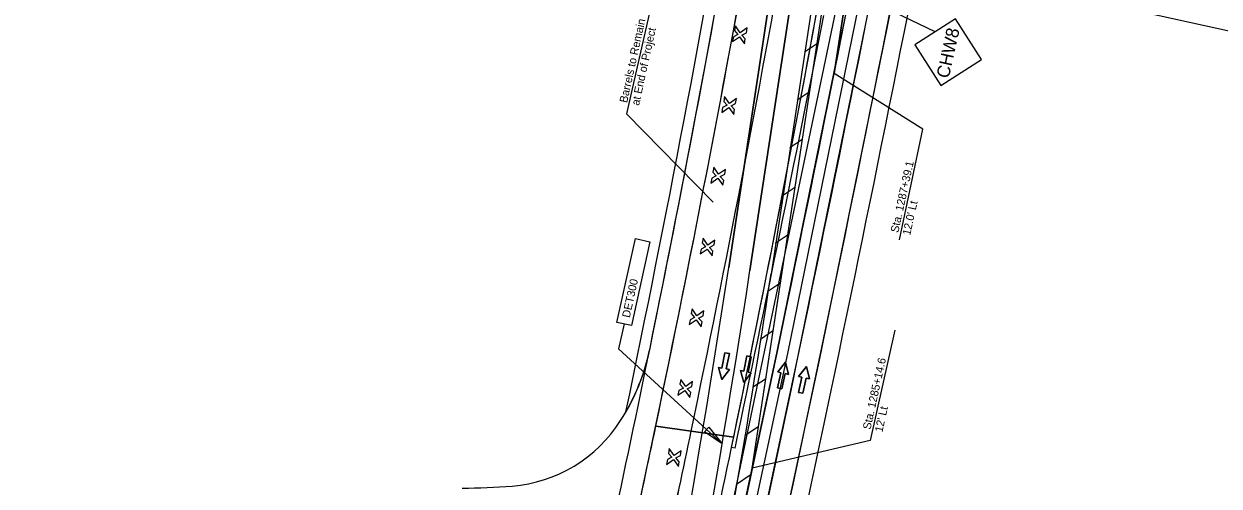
# Model space of a CAD drawing. Extents: x 14104283 to 14120882, y 8635219 to 8671666.
# Drawn here: x 14107490 to 14108160, y 8639477 to 8639736 of the extents above; entities that cross this region are included whole.
import ezdxf

# ---------------------------------------------------------------- set-up
doc = ezdxf.new("R2010")
doc.units = 0
for name, color, linetype in [('Cell', 7, 'Continuous'), ('dsnNonPlotable', 7, 'Continuous'), ('dsnPaintExistingBrokenLaneLineWhite', 7, 'Continuous'), ('dsnPaintExistingEdgeLineRightWhite', 7, 'Continuous'), ('dsnPaintPlaceBrokenLaneWhite', 7, 'Continuous'), ('dsnPaintPlaceChannelizingLaneWhite', 7, 'Continuous'), ('dsnPaintPlaceChannelizingLaneYellow', 7, 'Continuous'), ('dsnPaintPlaceEdgeLineRightWhite', 7, 'Continuous'), ('dsnPaintRemoveEdgeLineWhite', 7, 'Continuous'), ('dsnPaintRemoveEdgeLineYellow', 7, 'Continuous'), ('dsnShadingPaved', 7, 'Continuous'), ('dsnStdLabel', 7, 'Continuous'), ('dsnStgShadingPrevPav', 7, 'Continuous'), ('Text', 7, 'Continuous')]:
    doc.layers.add(name, color=color, linetype=linetype)

msp = doc.modelspace()

# ---------------------------------------------------------------- linework, layer by layer
at = {"layer": 'Cell'}
for p, q in [((14107889.07, 8639734.89), (14107888.6, 8639732.18)), ((14107891.81, 8639730.99), (14107889.07, 8639734.89)), ((14107895.72, 8639733.73), (14107891.81, 8639730.99)), ((14107895.25, 8639731.02), (14107895.72, 8639733.73)), ((14107887.52, 8639726.02), (14107891.43, 8639728.77)), ((14107888, 8639728.73), (14107887.52, 8639726.02)), ((14107890.51, 8639730.07), (14107888, 8639728.73)), ((14107888.6, 8639732.18), (14107890.51, 8639730.07)), ((14107891.43, 8639728.77), (14107894.17, 8639724.86)), ((14107892.73, 8639729.68), (14107895.25, 8639731.02)), ((14107894.65, 8639727.57), (14107892.73, 8639729.68)), ((14107894.17, 8639724.86), (14107894.65, 8639727.57)), ((14107883.03, 8639695.26), (14107882.55, 8639692.56)), ((14107885.77, 8639691.36), (14107883.03, 8639695.26)), ((14107889.68, 8639694.1), (14107885.77, 8639691.36)), ((14107889.2, 8639691.39), (14107889.68, 8639694.1)), ((14107881.48, 8639686.4), (14107885.38, 8639689.14)), ((14107881.95, 8639689.11), (14107881.48, 8639686.4)), ((14107884.47, 8639690.44), (14107881.95, 8639689.11)), ((14107882.55, 8639692.56), (14107884.47, 8639690.44)), ((14107885.38, 8639689.14), (14107888.13, 8639685.24)), ((14107886.68, 8639690.06), (14107889.2, 8639691.39)), ((14107888.6, 8639687.95), (14107886.68, 8639690.06)), ((14107888.13, 8639685.24), (14107888.6, 8639687.95)), ((14107876.96, 8639655.64), (14107876.48, 8639652.93)), ((14107876.48, 8639652.93), (14107878.4, 8639650.82)), ((14107879.7, 8639651.74), (14107876.96, 8639655.64)), ((14107883.61, 8639654.48), (14107879.7, 8639651.74)), ((14107883.13, 8639651.77), (14107883.61, 8639654.48)), ((14107875.41, 8639646.78), (14107879.31, 8639649.52)), ((14107875.88, 8639649.49), (14107875.41, 8639646.78)), ((14107878.4, 8639650.82), (14107875.88, 8639649.49)), ((14107879.31, 8639649.52), (14107882.06, 8639645.62)), ((14107880.62, 8639650.44), (14107883.13, 8639651.77)), ((14107882.53, 8639648.33), (14107880.62, 8639650.44)), ((14107882.06, 8639645.62), (14107882.53, 8639648.33)), ((14107870.97, 8639616.01), (14107870.49, 8639613.3)), ((14107870.49, 8639613.3), (14107872.41, 8639611.19)), ((14107873.71, 8639612.1), (14107870.97, 8639616.01)), ((14107877.62, 8639614.84), (14107873.71, 8639612.1)), ((14107877.14, 8639612.14), (14107877.62, 8639614.84)), ((14107869.42, 8639607.14), (14107873.32, 8639609.88)), ((14107869.89, 8639609.85), (14107869.42, 8639607.14)), ((14107872.41, 8639611.19), (14107869.89, 8639609.85)), ((14107873.32, 8639609.88), (14107876.07, 8639605.98)), ((14107874.63, 8639610.8), (14107877.14, 8639612.14)), ((14107876.54, 8639608.69), (14107874.63, 8639610.8)), ((14107876.07, 8639605.98), (14107876.54, 8639608.69)), ((14107864.82, 8639576.4), (14107864.35, 8639573.69)), ((14107864.35, 8639573.69), (14107866.26, 8639571.58)), ((14107867.56, 8639572.5), (14107864.82, 8639576.4)), ((14107871.47, 8639575.24), (14107867.56, 8639572.5)), ((14107868.48, 8639571.19), (14107871, 8639572.53)), ((14107871, 8639572.53), (14107871.47, 8639575.24)), ((14107863.27, 8639567.54), (14107867.18, 8639570.28)), ((14107863.75, 8639570.24), (14107863.27, 8639567.54)), ((14107866.26, 8639571.58), (14107863.75, 8639570.24)), ((14107867.18, 8639570.28), (14107869.92, 8639566.38)), ((14107870.4, 8639569.08), (14107868.48, 8639571.19)), ((14107869.92, 8639566.38), (14107870.4, 8639569.08)), ((14107858.48, 8639536.84), (14107858.01, 8639534.13)), ((14107858.01, 8639534.13), (14107859.93, 8639532.02)), ((14107861.23, 8639532.94), (14107858.48, 8639536.84)), ((14107865.13, 8639535.68), (14107861.23, 8639532.94)), ((14107862.14, 8639531.63), (14107864.66, 8639532.97)), ((14107864.66, 8639532.97), (14107865.13, 8639535.68)), ((14107856.93, 8639527.97), (14107860.84, 8639530.72)), ((14107857.41, 8639530.68), (14107856.93, 8639527.97)), ((14107859.93, 8639532.02), (14107857.41, 8639530.68)), ((14107860.84, 8639530.72), (14107863.58, 8639526.81)), ((14107864.06, 8639529.52), (14107862.14, 8639531.63)), ((14107863.58, 8639526.81), (14107864.06, 8639529.52)), ((14107853.51, 8639493.28), (14107850.99, 8639491.94)), ((14107852.07, 8639498.1), (14107851.59, 8639495.39)), ((14107851.59, 8639495.39), (14107853.51, 8639493.28)), ((14107854.81, 8639494.19), (14107852.07, 8639498.1)), ((14107858.71, 8639496.93), (14107854.81, 8639494.19)), ((14107855.72, 8639492.89), (14107858.24, 8639494.23)), ((14107857.64, 8639490.78), (14107855.72, 8639492.89)), ((14107858.24, 8639494.23), (14107858.71, 8639496.93)), ((14107850.52, 8639489.23), (14107854.42, 8639491.97)), ((14107850.99, 8639491.94), (14107850.52, 8639489.23)), ((14107854.42, 8639491.97), (14107857.17, 8639488.07)), ((14107857.17, 8639488.07), (14107857.64, 8639490.78))]:
    msp.add_line(p, q, dxfattribs=at)
for points in [[(14107883.26, 8639551.82), (14107885.71, 8639551.33), (14107884, 8639542.75), (14107885.84, 8639542.38), (14107881.55, 8639536.86), (14107879.71, 8639543.61), (14107881.55, 8639543.24)], [(14107895.45, 8639550.04), (14107897.9, 8639549.55), (14107896.18, 8639540.97), (14107898.02, 8639540.6), (14107893.73, 8639535.09), (14107891.89, 8639541.83), (14107893.73, 8639541.46)], [(14107915.2, 8639531.54), (14107912.75, 8639532.07), (14107914.62, 8639540.62), (14107912.79, 8639541.02), (14107917.17, 8639546.46), (14107918.89, 8639539.69), (14107917.06, 8639540.09)], [(14107926.93, 8639529.08), (14107924.49, 8639529.61), (14107926.35, 8639538.16), (14107924.52, 8639538.56), (14107928.91, 8639544), (14107930.63, 8639537.22), (14107928.8, 8639537.62)]]:
    msp.add_lwpolyline(points, close=True, dxfattribs=at)
for points in [[(14107881.55, 8639543.24), (14107879.71, 8639543.61), (14107881.55, 8639536.86), (14107885.84, 8639542.38), (14107884, 8639542.75), (14107885.71, 8639551.33), (14107883.26, 8639551.82), (14107881.55, 8639543.24)], [(14107893.73, 8639541.46), (14107891.89, 8639541.83), (14107893.73, 8639535.09), (14107898.02, 8639540.6), (14107896.18, 8639540.97), (14107897.9, 8639549.55), (14107895.45, 8639550.04), (14107893.73, 8639541.46)], [(14107917.06, 8639540.09), (14107918.89, 8639539.69), (14107917.17, 8639546.46), (14107912.79, 8639541.02), (14107914.62, 8639540.62), (14107912.75, 8639532.07), (14107915.2, 8639531.54), (14107917.06, 8639540.09)], [(14107928.8, 8639537.62), (14107930.63, 8639537.22), (14107928.91, 8639544), (14107924.52, 8639538.56), (14107926.35, 8639538.16), (14107924.49, 8639529.61), (14107926.93, 8639529.08), (14107928.8, 8639537.62)]]:
    msp.add_lwpolyline(points, dxfattribs=at)
at = {"layer": 'dsnNonPlotable'}
msp.add_lwpolyline([(14107490.45, 8639880.3), (14107826.84, 8641411.28), (14108813.31, 8641194.53), (14108476.92, 8639663.55)], close=True, dxfattribs=at)
at = {"layer": 'dsnPaintExistingBrokenLaneLineWhite'}
msp.add_line((14107897.23, 8639597.8), (14108002.8, 8640289.8), dxfattribs=at)
msp.add_arc((14101471.58, 8640578.08), 6500, 347.610212, 351.325989, dxfattribs=at)
at = {"layer": 'dsnPaintExistingEdgeLineRightWhite'}
msp.add_line((14107908.71, 8639752.63), (14107885.37, 8639599.61), dxfattribs=at)
msp.add_arc((14101471.58, 8640578.08), 6488, 347.610212, 351.325989, dxfattribs=at)
at = {"layer": 'dsnPaintPlaceBrokenLaneWhite'}
msp.add_lwpolyline([(14107843.64, 8639178.31), (14107884.58, 8639364.68), (14107924.33, 8639550.14), (14107962.2, 8639735.99), (14107989.47, 8639873.39), (14108016.73, 8640010.79)], dxfattribs=at)
at = {"layer": 'dsnPaintPlaceChannelizingLaneWhite'}
for p, q in [((14107944.41, 8639708.12), (14107967.03, 8639856.41)), ((14107946.08, 8639716.5), (14107945.64, 8639716.21))]:
    msp.add_line(p, q, dxfattribs=at)
msp.add_lwpolyline([(14107944.41, 8639708.12), (14107950.42, 8639738.27), (14107973.63, 8639855.23)], dxfattribs=at)
at = {"layer": 'dsnPaintPlaceChannelizingLaneYellow'}
for p, q in [((14107898.55, 8639487.12), (14107955.17, 8639858.22)), ((14107949.23, 8639859.12), (14107909.09, 8639595.99)), ((14107934.5, 8639724.59), (14107927.73, 8639720.06)), ((14107930.41, 8639697.79), (14107923.65, 8639693.27)), ((14107926.32, 8639671), (14107919.56, 8639666.47)), ((14107922.23, 8639644.2), (14107915.47, 8639639.68)), ((14107918.15, 8639617.41), (14107911.39, 8639612.89)), ((14107914.06, 8639590.61), (14107907.29, 8639586.08)), ((14107909.97, 8639563.82), (14107903.09, 8639559.21)), ((14107905.88, 8639537.02), (14107898.76, 8639532.26)), ((14107901.8, 8639510.23), (14107894.3, 8639505.21)), ((14107897.42, 8639483.24), (14107889.71, 8639478.08))]:
    msp.add_line(p, q, dxfattribs=at)
msp.add_lwpolyline([(14107831.92, 8639180.86), (14107872.85, 8639367.2), (14107898.55, 8639487.12)], dxfattribs=at)
msp.add_arc((14101471.58, 8640578.08), 6512, 349.4681, 351.325989, dxfattribs=at)
at = {"layer": 'dsnPaintPlaceEdgeLineRightWhite'}
msp.add_line((14107973.96, 8639733.6), (14107997.25, 8639850.98), dxfattribs=at)
msp.add_arc((14089678.7, 8643364.11), 18652, 347.610212, 348.776036, dxfattribs=at)
at = {"layer": 'dsnPaintRemoveEdgeLineWhite'}
msp.add_lwpolyline([(14107811.17, 8639057.08), (14107844.94, 8639211.53), (14107878.72, 8639365.97), (14107918.46, 8639551.34), (14107956.3, 8639737.1), (14108010.84, 8640011.94), (14108059.95, 8640246.87), (14108093.19, 8640398.18)], dxfattribs=at)
at = {"layer": 'dsnPaintRemoveEdgeLineYellow'}
msp.add_lwpolyline([(14107799.44, 8639059.65), (14107867, 8639368.55), (14107944.53, 8639739.44), (14107999.07, 8640014.27), (14108048.23, 8640249.45), (14108081.5, 8640400.87)], dxfattribs=at)
at = {"layer": 'dsnShadingPaved'}
for p, q in [((14107885.37, 8639599.61), (14107990.94, 8640291.61)), ((14108002.8, 8640289.8), (14107897.23, 8639597.8)), ((14107897.23, 8639597.8), (14107955.22, 8639977.91)), ((14107897.98, 8639483.38), (14107955.17, 8639858.22)), ((14107949.23, 8639859.12), (14107909.09, 8639595.99)), ((14107967.03, 8639856.41), (14107944.41, 8639708.12))]:
    msp.add_line(p, q, dxfattribs=at)
for points in [[(14107831.92, 8639180.86), (14107872.85, 8639367.2), (14107912.58, 8639552.57), (14107950.43, 8639738.33), (14108004.96, 8640013.11)], [(14108028.5, 8640008.43), (14107973.96, 8639733.6), (14107936.08, 8639547.66), (14107896.3, 8639362.11), (14107855.36, 8639175.71)], [(14107944.81, 8639710.74), (14107912.58, 8639552.57), (14107898.55, 8639487.12)]]:
    msp.add_lwpolyline(points, dxfattribs=at)
for radius, start in [(6488, 347.610212), (6500, 347.610212), (6500, 347.610212), (6512, 349.4681)]:
    msp.add_arc((14101471.58, 8640578.08), radius, start, 351.325989, dxfattribs=at)
at = {"layer": 'dsnStdLabel'}
msp.add_line((14108000.99, 8639731.5), (14107953.61, 8639754.35), dxfattribs=at)
msp.add_lwpolyline([(14108004.17, 8639701.48), (14108026.91, 8639716.03), (14108012.36, 8639738.77), (14107989.62, 8639724.22)], close=True, dxfattribs=at)
at = {"layer": 'dsnStgShadingPrevPav'}
for p, q in [((14107983.77, 8639731.65), (14108038.31, 8640006.49)), ((14107864.34, 8639507.93), (14107844.49, 8639510.73)), ((14107844.5, 8639510.74), (14107864.35, 8639507.93)), ((14107864.34, 8639507.93), (14107888.16, 8639504.57)), ((14107888.16, 8639504.57), (14107864.34, 8639507.93)), ((14107888.89, 8639498.33), (14107886.94, 8639498.75)), ((14107888.89, 8639498.33), (14107886.94, 8639498.75))]:
    msp.add_line(p, q, dxfattribs=at)
for centre, radius, start, end in [((14098576.76, 8641447.78), 9468, 347.807255, 351.672846), ((14098576.76, 8641447.78), 9456, 348.449343, 351.672846), ((14098576.76, 8641447.78), 9468, 348.194582, 351.672846), ((14098576.76, 8641447.78), 9488, 348.202524, 351.672846), ((14098576.76, 8641447.78), 9488, 348.202524, 351.672846), ((14098576.76, 8641447.78), 9512, 348.176197, 351.653537), ((14098576.76, 8641447.78), 9512, 348.212012, 351.653537), ((14098576.76, 8641447.78), 9450, 348.220778, 350.242299), ((14098576.76, 8641447.78), 9456, 348.449343, 350.195701), ((14089678.7, 8643364.11), 18616, 348.014807, 348.776036), ((14089678.7, 8643364.11), 18616, 348.014807, 348.776036), ((14089678.7, 8643364.11), 18628, 347.714997, 348.776036), ((14089678.7, 8643364.11), 18628, 347.714933, 348.776036), ((14089678.7, 8643364.11), 18640, 347.714933, 348.776036), ((14089678.7, 8643364.11), 18640, 347.714933, 348.776036), ((14089678.7, 8643364.11), 18662, 347.714933, 348.776036), ((14098576.76, 8641447.78), 9456, 347.807393, 348.449343), ((14098576.76, 8641447.78), 9456, 347.807393, 348.449343), ((14107723.69, 8639578.39), 120, 327.40987, 348.44934), ((14107723.69, 8639578.39), 120, 330.13984, 348.44934), ((14107757.39, 8639556.85), 80, 274.70905, 327.40987), ((14098576.77, 8641447.78), 9468, 347.807255, 348.194582), ((14098576.76, 8641447.78), 9488, 347.807026, 348.202524), ((14098576.77, 8641447.78), 9488, 347.807026, 348.202524), ((14098576.76, 8641447.78), 9512, 348.176197, 348.212012), ((14098576.76, 8641447.78), 9512, 347.610212, 348.176197), ((14098576.76, 8641447.78), 9512, 347.610212, 348.176197), ((14107737.69, 8639796.04), 320, 269.69175, 274.70905)]:
    msp.add_arc(centre, radius, start, end, dxfattribs=at)
at = {"layer": 'Text'}
for points in [[(14107844.39, 8639757.3), (14107828.16, 8639685.56), (14107876.64, 8639636.14)], [(14107980.96, 8639614.96), (14107994.19, 8639676.97), (14107944.41, 8639708.12)], [(14107826.81, 8639567.9), (14107823.66, 8639553.95), (14107881.68, 8639500.81)], [(14107978.51, 8639564.45), (14107964.53, 8639502.61), (14107898.55, 8639487.12)]]:
    msp.add_lwpolyline(points, dxfattribs=at)
for points in [[(14107822.71, 8639568.81), (14107833.03, 8639615.79), (14107841.24, 8639613.99), (14107830.91, 8639567)], [(14107822.71, 8639568.81), (14107833.03, 8639615.79), (14107841.24, 8639613.99), (14107830.91, 8639567)], [(14107881.68, 8639500.81), (14107871.78, 8639507.48), (14107874.17, 8639510.1)]]:
    msp.add_lwpolyline(points, close=True, dxfattribs=at)

# ---------------------------------------------------------------- texts
at = {"layer": 'dsnStdLabel'}
msp.add_text('CHW8', height=7.2, rotation=77.60784, dxfattribs=at).set_placement((14108008.65, 8639705.11))
at = {"layer": 'Text'}
for s, height, p in [('Barrels to Remain', 4.4845, (14107828.4, 8639691.44)), ('at End of Project', 4.4845, (14107835.09, 8639689.97)), ('Sta. 1287+39.1', 4.4845, (14107980.34, 8639618.75)), ("12.0' Lt", 4.484, (14107987.03, 8639617.28)), ('DET300', 4.484, (14107829.88, 8639571.11)), ('Sta. 1285+14.6', 4.4845, (14107964.76, 8639508.49)), ("12' Lt", 4.484, (14107971.45, 8639507.02))]:
    msp.add_text(s, height=height, rotation=77.60784, dxfattribs=at).set_placement(p)

doc.saveas('drawing.dxf')
